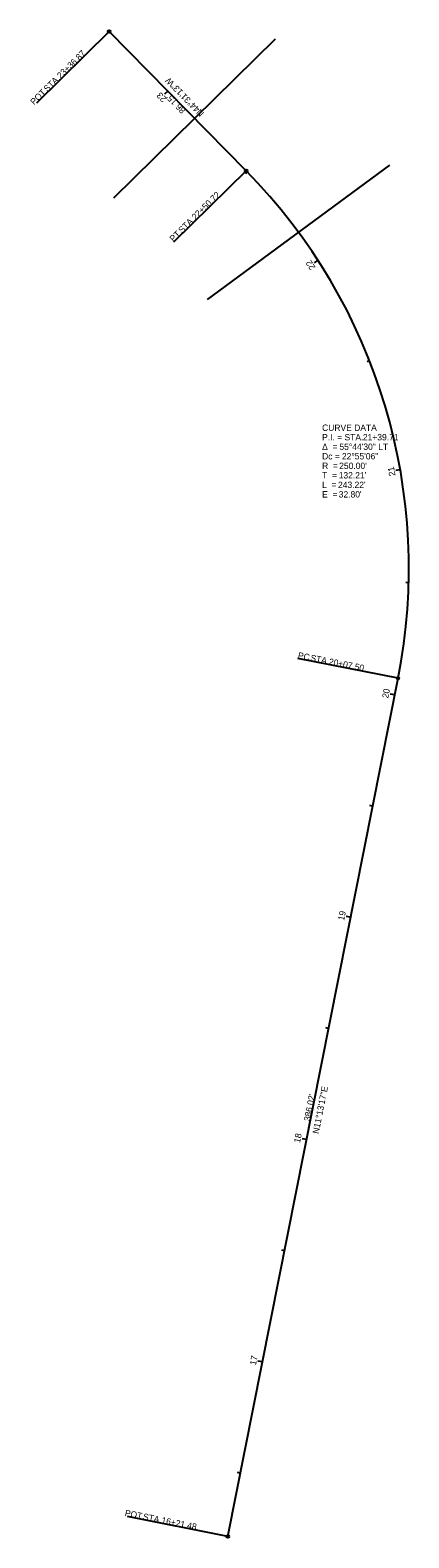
# Model space of a CAD drawing. Extents: x 147873 to 148040, y 486745 to 487410.
import ezdxf

# ---------------------------------------------------------------- set-up
doc = ezdxf.new("R2010")
doc.units = 0
for name, color, linetype in [('GE_X_Alignment', 7, 'Continuous'), ('GE_X_Alignment_100_Bearings', 7, 'Continuous'), ('GE_X_Alignment_100_Cardinal_Points', 7, 'Continuous'), ('GE_X_Alignment_100_Curve_Data', 7, 'Continuous'), ('GE_X_Alignment_100_Distances', 7, 'Continuous'), ('GE_X_Alignment_100_Stations', 7, 'Continuous'), ('PV_X_COP', 7, 'Continuous'), ('RW_X_CL', 7, 'Continuous')]:
    doc.layers.add(name, color=color, linetype=linetype)

msp = doc.modelspace()

# ---------------------------------------------------------------- linework, layer by layer
at = {"layer": 'GE_X_Alignment'}
for p, q in [((147968.09, 487348.44), (147907.69, 487409.87)), ((147959.94, 486745.86), (148035.06, 487124.5))]:
    msp.add_line(p, q, dxfattribs=at)
msp.add_arc((147789.84, 487173.15), 250, 348.77859, 44.52025, dxfattribs=at)
at = {"layer": 'GE_X_Alignment_100_Cardinal_Points'}
for p, q in [((147907.69, 487409.87), (147875.6, 487378.32)), ((147968.09, 487348.44), (147936.01, 487316.89)), ((148035.06, 487124.5), (147990.92, 487133.26)), ((147959.94, 486745.86), (147915.8, 486754.62))]:
    msp.add_line(p, q, dxfattribs=at)
for centre in [(147907.69, 487409.87), (147968.09, 487348.44), (148035.06, 487124.5), (147959.94, 486745.86)]:
    msp.add_circle(centre, 0.6, dxfattribs=at)
at = {"layer": 'GE_X_Alignment_100_Stations'}
for p, q in [((147933.54, 487383.58), (147932.11, 487382.18)), ((147968.59, 487347.93), (147967.74, 487347.09)), ((147999.75, 487308.93), (147998.07, 487307.85)), ((148022.55, 487264.52), (148021.43, 487264.09)), ((148036.06, 487216.47), (148034.09, 487216.13)), ((148039.76, 487166.69), (148038.56, 487166.72)), ((148033.6, 487117.15), (148031.64, 487117.54)), ((148023.87, 487068.1), (148022.69, 487068.34)), ((148014.14, 487019.06), (148012.18, 487019.45)), ((148004.41, 486970.01), (148003.23, 486970.25)), ((147994.68, 486920.97), (147992.72, 486921.36)), ((147984.95, 486871.93), (147983.77, 486872.16)), ((147975.22, 486822.88), (147973.26, 486823.27)), ((147965.49, 486773.84), (147964.31, 486774.07))]:
    msp.add_line(p, q, dxfattribs=at)
at = {"layer": 'PV_X_COP'}
for p, q in [((147909.76, 487336.45), (147981.06, 487406.57)), ((147950.96, 487291.65), (148031.51, 487350.9))]:
    msp.add_line(p, q, dxfattribs=at)
at = {"layer": 'RW_X_CL'}
msp.add_arc((147789.84, 487173.15), 250, 348.77859, 44.52025, dxfattribs=at)

# ---------------------------------------------------------------- texts
at = {"layer": 'GE_X_Alignment_100_Bearings'}
for s, rotation, p in [('N44°31\'13"W', 134.52025, (147949.75, 487373.94)), ('N11°13\'17"E', 78.77859, (148000.05, 486923.35))]:
    msp.add_text(s, height=2.8, rotation=rotation, dxfattribs=at).set_placement(p)
at = {"layer": 'GE_X_Alignment_100_Cardinal_Points'}
for s, rotation, p in [('23+36.87', 44.52025, (147886.27, 487388.86)), ('POT', 44.52025, (147874.53, 487377.32)), (' STA. ', 44.52025, (147879.62, 487382.32)), ('22+50.72', 44.52025, (147945.7, 487326.48)), (' STA. ', 44.52025, (147939.06, 487319.94)), ('PT', 44.52025, (147935.95, 487316.89)), ('PC', 348.77859, (147990.71, 487133.34)), (' STA. ', 348.77859, (147995.23, 487132.44)), ('20+07.50', 348.77859, (148004.37, 487130.63)), ('POT', 348.77859, (147914.37, 486754.94)), (' STA. ', 348.77859, (147921.36, 486753.55)), ('16+21.48', 348.77859, (147930.51, 486751.74))]:
    msp.add_text(s, height=2.8, rotation=rotation, dxfattribs=at).set_placement(p)
at = {"layer": 'GE_X_Alignment_100_Curve_Data'}
for s, p in [('CURVE DATA', (148001.58, 487233.67)), ('P.I. = STA. ', (148001.58, 487229.47)), ('21+39.71', (148019.57, 487229.47)), ('Δ  = ', (148001.58, 487225.27)), ('Dc = ', (148001.58, 487221.07)), ('55°44\'30" LT', (148009.22, 487225.27)), ('22°55\'06"', (148010.32, 487221.07)), ('R  = ', (148001.58, 487216.87)), ("250.00'", (148009.11, 487216.87)), ('T  = ', (148001.58, 487212.67)), ('L  = ', (148001.58, 487208.47)), ("243.22'", (148008.61, 487208.47)), ("132.21'", (148008.9, 487212.67)), ('E  = ', (148001.58, 487204.27)), ("32.80'", (148008.92, 487204.27))]:
    msp.add_text(s, height=2.8, dxfattribs=at).set_placement(p)
at = {"layer": 'GE_X_Alignment_100_Distances'}
for s, rotation, p in [("86.15'", 134.52025, (147941.59, 487375.34)), ("386.02'", 78.77859, (147996.21, 486928.88))]:
    msp.add_text(s, height=2.8, rotation=rotation, dxfattribs=at).set_placement(p)
at = {"layer": 'GE_X_Alignment_100_Stations'}
for s, rotation, p in [('23', 134.52025, (147933.21, 487380.35)), ('22', 122.89634, (147998.79, 487305.82)), ('21', 99.97803, (148033.96, 487213.96)), ('20', 78.77859, (148030.73, 487115.52)), ('19', 78.77859, (148011.28, 487017.48)), ('18', 78.77859, (147991.81, 486919.37)), ('17', 78.77859, (147972.36, 486821.28))]:
    msp.add_text(s, height=2.8, rotation=rotation, dxfattribs=at).set_placement(p)

doc.saveas('drawing.dxf')
